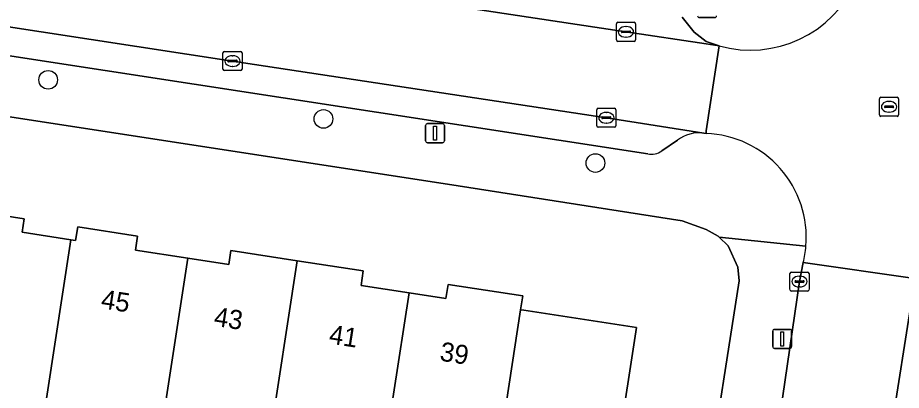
# Model space of a CAD drawing. Extents: x 161483 to 162250, y 379484 to 380833.
# Drawn here: x 161963.9 to 162010.23, y 380518.15 to 380537.71 of the extents above; entities that cross this region are included whole.
import ezdxf

# ---------------------------------------------------------------- set-up
doc = ezdxf.new("R2010")
doc.units = 0
for name, color, linetype in [('IMGEO_Boom', 7, 'Continuous'), ('IMGEO_Erf', 7, 'Continuous'), ('IMGEO_Kolk', 7, 'Continuous'), ('IMGEO_Lichtmast', 7, 'Continuous'), ('IMGEO_Pand', 7, 'Continuous'), ('IMGEO_Pand_nummerreeks', 7, 'Continuous'), ('IMGEO_Parkeervlak_open', 7, 'Continuous'), ('IMGEO_Rijbaan_lokaal_open', 7, 'Continuous'), ('IMGEO_Rioolput', 7, 'Continuous'), ('IMGEO_Voetpad_open', 7, 'Continuous')]:
    doc.layers.add(name, color=color, linetype=linetype)

msp = doc.modelspace()

# ---------------------------------------------------------------- linework, layer by layer
at = {"layer": 'IMGEO_Boom'}
for centre in [(161965.497, 380534.445), (161979.932, 380532.394), (161994.191, 380530.079)]:
    msp.add_circle(centre, 0.489, dxfattribs=at)
at = {"layer": 'IMGEO_Erf'}
for points in [[(162001.728, 380523.906), (162001.658, 380524.62), (162001.144, 380525.735), (162000.674, 380526.189), (162000.627, 380526.234), (162000, 380526.588), (161998.738, 380527.044), (161986.998, 380528.881), (161932.112, 380537.338)], [(161960.869, 380527.668), (161964.235, 380527.151), (161964.127, 380526.446), (161966.695, 380526.052), (161966.94, 380526.014), (161967.05, 380526.73), (161970.184, 380526.248), (161970.069, 380525.501), (161972.814, 380525.079), (161974.966, 380524.748), (161975.079, 380525.482), (161978.56, 380524.947), (161982.017, 380524.415), (161981.901, 380523.66), (161984.425, 380523.272), (161986.351, 380522.976), (161986.464, 380523.708), (161990.381, 380523.106), (161990.27, 380522.381), (161990.445, 380522.354), (161996.342, 380521.448), (161994.423, 380508.962)], [(162000, 380512.813), (162001.728, 380523.906)]]:
    msp.add_lwpolyline(points, dxfattribs=at)
at = {"layer": 'IMGEO_Kolk'}
for p, q in [((161995.292, 380536.539), (161995.292, 380537.391)), ((161995.367, 380537.465), (161996.219, 380537.465)), ((161995.78, 380537.245), (161995.805, 380537.245)), ((161996.293, 380537.391), (161996.293, 380536.539)), ((161995.551, 380536.959), (161995.551, 380536.971)), ((161995.989, 380536.922), (161995.591, 380536.922)), ((161995.594, 380537.008), (161995.992, 380537.008)), ((161996.035, 380536.971), (161996.035, 380536.959)), ((161996.219, 380536.465), (161995.367, 380536.465)), ((161995.803, 380536.685), (161995.778, 380536.685)), ((161974.662, 380535.005), (161974.662, 380535.857)), ((161974.737, 380535.931), (161975.589, 380535.931)), ((161975.663, 380535.857), (161975.663, 380535.005)), ((161974.921, 380535.425), (161974.921, 380535.437)), ((161975.359, 380535.388), (161974.961, 380535.388)), ((161974.964, 380535.474), (161975.362, 380535.474)), ((161975.15, 380535.711), (161975.175, 380535.711)), ((161975.405, 380535.437), (161975.405, 380535.425)), ((161975.589, 380534.931), (161974.737, 380534.931)), ((161975.173, 380535.151), (161975.148, 380535.151)), ((161994.263, 380532.028), (161994.263, 380532.88)), ((161994.338, 380532.954), (161995.19, 380532.954)), ((161994.751, 380532.734), (161994.776, 380532.734)), ((161995.264, 380532.88), (161995.264, 380532.028)), ((161994.522, 380532.448), (161994.522, 380532.46)), ((161994.96, 380532.411), (161994.562, 380532.411)), ((161994.565, 380532.497), (161994.963, 380532.497)), ((161994.774, 380532.174), (161994.749, 380532.174)), ((161995.006, 380532.46), (161995.006, 380532.448)), ((161995.19, 380531.954), (161994.338, 380531.954)), ((162004.389, 380523.434), (162004.389, 380524.286)), ((162004.464, 380524.36), (162005.316, 380524.36)), ((162005.39, 380524.286), (162005.39, 380523.434)), ((162004.648, 380523.854), (162004.648, 380523.866)), ((162005.086, 380523.817), (162004.688, 380523.817)), ((162004.691, 380523.903), (162005.089, 380523.903)), ((162004.877, 380524.14), (162004.902, 380524.14)), ((162005.132, 380523.866), (162005.132, 380523.854)), ((162005.316, 380523.36), (162004.464, 380523.36)), ((162004.9, 380523.58), (162004.875, 380523.58))]:
    msp.add_line(p, q, dxfattribs=at)
for points in [[(161995.292, 380536.539), (161995.292, 380537.391)], [(161995.367, 380537.465), (161996.219, 380537.465)], [(161996.293, 380537.391), (161996.293, 380536.539)], [(161996.219, 380536.465), (161995.367, 380536.465)], [(161974.662, 380535.005), (161974.662, 380535.857)], [(161974.737, 380535.931), (161975.589, 380535.931)], [(161975.663, 380535.857), (161975.663, 380535.005)], [(161975.589, 380534.931), (161974.737, 380534.931)], [(161994.263, 380532.028), (161994.263, 380532.88)], [(161994.338, 380532.954), (161995.19, 380532.954)], [(161995.264, 380532.88), (161995.264, 380532.028)], [(161995.19, 380531.954), (161994.338, 380531.954)], [(162004.389, 380523.434), (162004.389, 380524.286)], [(162004.464, 380524.36), (162005.316, 380524.36)], [(162005.39, 380524.286), (162005.39, 380523.434)], [(162005.316, 380523.36), (162004.464, 380523.36)]]:
    msp.add_lwpolyline(points, dxfattribs=at)
for centre, radius, start, end in [((161995.369, 380537.389), 0.0765, 91.552, 178.448), ((161995.369, 380537.389), 0.0765, 91.552, 178.448), ((161996.217, 380537.389), 0.0765, 1.552, 88.448), ((161996.217, 380537.389), 0.0765, 1.552, 88.448), ((161995.591, 380536.968), 0.0403, 85.8775, 175.7526), ((161995.588, 380536.958), 0.0366, 178.938, 274.7102), ((161995.992, 380536.965), 0.043, 264.8664, 352.4533), ((161995.996, 380536.97), 0.0386, 1.7309, 96.639), ((161995.369, 380536.541), 0.0765, 181.552, 268.448), ((161995.369, 380536.541), 0.0765, 181.552, 268.448), ((161996.217, 380536.541), 0.0765, 271.552, 358.448), ((161996.217, 380536.541), 0.0765, 271.552, 358.448), ((161974.739, 380535.855), 0.0765, 91.552, 178.448), ((161974.739, 380535.855), 0.0765, 91.552, 178.448), ((161975.587, 380535.855), 0.0765, 1.552, 88.448), ((161975.587, 380535.855), 0.0765, 1.552, 88.448), ((161974.961, 380535.434), 0.0403, 85.8775, 175.7526), ((161974.958, 380535.424), 0.0366, 178.938, 274.7102), ((161975.362, 380535.431), 0.043, 264.8664, 352.4533), ((161975.366, 380535.436), 0.0386, 1.7309, 96.639), ((161974.739, 380535.007), 0.0765, 181.552, 268.448), ((161974.739, 380535.007), 0.0765, 181.552, 268.448), ((161975.587, 380535.007), 0.0765, 271.552, 358.448), ((161975.587, 380535.007), 0.0765, 271.552, 358.448), ((161994.34, 380532.878), 0.0765, 91.552, 178.448), ((161994.34, 380532.878), 0.0765, 91.552, 178.448), ((161995.188, 380532.878), 0.0765, 1.552, 88.448), ((161995.188, 380532.878), 0.0765, 1.552, 88.448), ((161994.562, 380532.457), 0.0403, 85.8775, 175.7526), ((161994.559, 380532.447), 0.0366, 178.938, 274.7102), ((161994.963, 380532.454), 0.043, 264.8664, 352.4533), ((161994.967, 380532.459), 0.0386, 1.7309, 96.639), ((161994.34, 380532.03), 0.0765, 181.552, 268.448), ((161994.34, 380532.03), 0.0765, 181.552, 268.448), ((161995.188, 380532.03), 0.0765, 271.552, 358.448), ((161995.188, 380532.03), 0.0765, 271.552, 358.448), ((162004.466, 380524.284), 0.0765, 91.552, 178.448), ((162004.466, 380524.284), 0.0765, 91.552, 178.448), ((162005.314, 380524.284), 0.0765, 1.552, 88.448), ((162005.314, 380524.284), 0.0765, 1.552, 88.448), ((162004.688, 380523.863), 0.0403, 85.8775, 175.7526), ((162004.685, 380523.853), 0.0366, 178.938, 274.7102), ((162005.089, 380523.86), 0.043, 264.8664, 352.4533), ((162005.093, 380523.865), 0.0386, 1.7309, 96.639), ((162004.466, 380523.436), 0.0765, 181.552, 268.448), ((162004.466, 380523.436), 0.0765, 181.552, 268.448), ((162005.314, 380523.436), 0.0765, 271.552, 358.448), ((162005.314, 380523.436), 0.0765, 271.552, 358.448)]:
    msp.add_arc(centre, radius, start, end, dxfattribs=at)
for centre, major_axis, ratio, start_param, end_param in [((161995.779, 380536.965), (-0.387, 0.002), 0.722429, 4.712389, 7.853982), ((161995.804, 380536.965), (-0.39, 0.002), 0.717154, 1.570796, 4.712389), ((161975.149, 380535.431), (-0.387, 0.002), 0.722429, 4.712389, 7.853982), ((161975.174, 380535.431), (-0.39, 0.002), 0.717154, 1.570796, 4.712389), ((161994.75, 380532.454), (-0.387, 0.002), 0.722429, 4.712389, 7.853982), ((161994.775, 380532.454), (-0.39, 0.002), 0.717154, 1.570796, 4.712389), ((162004.876, 380523.86), (-0.387, 0.002), 0.722429, 4.712389, 7.853982), ((162004.901, 380523.86), (-0.39, 0.002), 0.717154, 1.570796, 4.712389)]:
    msp.add_ellipse(centre, major_axis=major_axis, ratio=ratio, start_param=start_param, end_param=end_param, dxfattribs=at)
at = {"layer": 'IMGEO_Lichtmast'}
for p, q in [((162000.439, 380537.709), (161999.649, 380537.709)), ((161999.649, 380537.709), (162000.439, 380537.709)), ((161985.386, 380532.148), (161986.176, 380532.148)), ((161986.176, 380532.148), (161985.386, 380532.148)), ((161985.286, 380531.248), (161985.286, 380532.048)), ((161985.286, 380532.048), (161985.286, 380531.248)), ((161986.276, 380532.048), (161986.276, 380531.248)), ((161986.276, 380531.248), (161986.276, 380532.048)), ((161986.176, 380531.148), (161985.386, 380531.148)), ((161985.386, 380531.148), (161986.176, 380531.148)), ((162003.485, 380520.448), (162003.485, 380521.248)), ((162003.485, 380521.248), (162003.485, 380520.448)), ((162003.585, 380521.348), (162004.375, 380521.348)), ((162004.375, 380521.348), (162003.585, 380521.348)), ((162004.475, 380521.248), (162004.475, 380520.448)), ((162004.475, 380520.448), (162004.475, 380521.248)), ((162004.375, 380520.348), (162003.585, 380520.348)), ((162003.585, 380520.348), (162004.375, 380520.348))]:
    msp.add_line(p, q, dxfattribs=at)
for points in [[(161985.706, 380532.023), (161985.856, 380532.023), (161985.856, 380531.273), (161985.706, 380531.273), (161985.706, 380532.023)], [(162003.905, 380521.223), (162004.055, 380521.223), (162004.055, 380520.473), (162003.905, 380520.473), (162003.905, 380521.223)]]:
    msp.add_lwpolyline(points, dxfattribs=at)
for centre, start, end in [((161999.649, 380537.809), 180, 270), ((161999.649, 380537.809), 180, 270), ((162000.439, 380537.809), 270, 0), ((162000.439, 380537.809), 270, 0), ((161985.386, 380532.048), 90, 180), ((161985.386, 380532.048), 90, 180), ((161986.176, 380532.048), 0, 90), ((161986.176, 380532.048), 360, 90), ((161985.386, 380531.248), 180, 270), ((161985.386, 380531.248), 180, 270), ((161986.176, 380531.248), 270, 0), ((161986.176, 380531.248), 270, 0), ((162003.585, 380521.248), 90, 180), ((162003.585, 380521.248), 90, 180), ((162004.375, 380521.248), 0, 90), ((162004.375, 380521.248), 360, 90), ((162003.585, 380520.448), 180, 270), ((162003.585, 380520.448), 180, 270), ((162004.375, 380520.448), 270, 0), ((162004.375, 380520.448), 270, 0)]:
    msp.add_arc(centre, 0.1, start, end, dxfattribs=at)
at = {"layer": 'IMGEO_Pand'}
for points in [[(161966.695, 380526.052), (161964.127, 380526.446), (161964.235, 380527.151), (161960.869, 380527.668), (161959.381, 380517.981), (161959.162, 380516.28), (161959.156, 380516.237), (161965.048, 380515.332)], [(161972.814, 380525.079), (161970.069, 380525.501), (161970.184, 380526.248), (161967.05, 380526.73), (161966.94, 380526.014), (161966.695, 380526.052), (161965.048, 380515.332), (161965.15, 380515.316), (161968.125, 380514.865), (161971.173, 380514.397)], [(161978.56, 380524.947), (161975.079, 380525.482), (161974.966, 380524.748), (161972.814, 380525.079), (161971.173, 380514.397), (161973.602, 380514.024), (161976.807, 380513.532), (161977.073, 380515.263)], [(161977.073, 380515.263), (161980.139, 380514.792), (161979.877, 380513.082), (161982.791, 380512.634), (161984.425, 380523.272), (161981.901, 380523.66), (161982.017, 380524.415), (161978.56, 380524.947)], [(161990.27, 380522.381), (161990.381, 380523.106), (161986.464, 380523.708), (161986.351, 380522.976), (161984.425, 380523.272), (161982.791, 380512.634), (161982.508, 380510.793), (161988.352, 380509.895), (161988.911, 380513.534)], [(161996.342, 380521.448), (161990.445, 380522.354), (161990.27, 380522.381), (161988.911, 380513.534), (161988.352, 380509.895), (161991.806, 380509.364), (161994.423, 380508.962)]]:
    msp.add_lwpolyline(points, close=True, dxfattribs=at)
at = {"layer": 'IMGEO_Parkeervlak_open'}
for points in [[(161929.69, 380547.086), (161933.264, 380546.55), (161935.372, 380546.247), (161952.528, 380543.603), (161973.878, 380540.297), (161995.793, 380536.963), (162000, 380536.329), (162000.684, 380536.226), (162000, 380536.452), (161999.367, 380536.946), (161998.747, 380537.733)], [(161999.874, 380531.653), (161994.763, 380532.455), (161975.164, 380535.431), (161952.685, 380538.893), (161936.805, 380541.351), (161932.606, 380542.007)], [(161935.118, 380540.075), (161996.932, 380530.558)], [(161997.666, 380530.714), (161998.496, 380531.281)]]:
    msp.add_lwpolyline(points, dxfattribs=at)
for centre, radius, start, end in [((161999.638, 380529.787), 1.881, 82.8041, 127.4104), ((161997.108, 380531.536), 0.994, 259.818, 304.1795)]:
    msp.add_arc(centre, radius, start, end, dxfattribs=at)
at = {"layer": 'IMGEO_Rijbaan_lokaal_open'}
msp.add_lwpolyline([(161933.264, 380546.55), (161932.606, 380542.007), (161936.805, 380541.351), (161952.685, 380538.893), (161975.164, 380535.431), (161994.763, 380532.455), (161999.874, 380531.653), (162000, 380531.633), (162000, 380531.772), (162000.684, 380536.226), (162000, 380536.329), (161995.793, 380536.963), (161973.878, 380540.297), (161952.528, 380543.603), (161935.372, 380546.247)], close=True, dxfattribs=at)
for points in [[(162000.684, 380536.226), (162000, 380531.772), (162000, 380531.633)], [(162005.978, 380491.592), (162006.784, 380496.829), (162007.271, 380500), (162009.728, 380516.285), (162010.756, 380522.832), (162010.932, 380524.02), (162005.085, 380524.854), (162004.891, 380523.86), (162003.878, 380516.894), (162001.249, 380500), (162000.753, 380496.771), (162000.066, 380492.294), (162000, 380492.002), (161999.789, 380491.531), (161999.389, 380490.794), (161999.112, 380490.027), (161990.029, 380431.608)], [(162005.085, 380524.854), (162010.932, 380524.02)]]:
    msp.add_lwpolyline(points, dxfattribs=at)
for centre, radius, start, end in [((162002.309, 380542.092), 6.087, 254.5191, 335.7592), ((161999.786, 380526.176), 5.461, 355.1673, 87.7575), ((161999.863, 380526.163), 5.384, 345.9264, 355.2352)]:
    msp.add_arc(centre, radius, start, end, dxfattribs=at)
at = {"layer": 'IMGEO_Rioolput'}
for p, q in [((162009.16, 380533.531), (162010.012, 380533.531)), ((162009.085, 380532.605), (162009.085, 380533.457)), ((162009.387, 380533.074), (162009.785, 380533.074)), ((162009.573, 380533.311), (162009.598, 380533.311)), ((162010.086, 380533.457), (162010.086, 380532.605)), ((162009.344, 380533.025), (162009.344, 380533.037)), ((162009.782, 380532.988), (162009.384, 380532.988)), ((162009.596, 380532.751), (162009.571, 380532.751)), ((162009.828, 380533.037), (162009.828, 380533.025)), ((162010.012, 380532.531), (162009.16, 380532.531))]:
    msp.add_line(p, q, dxfattribs=at)
for points in [[(162009.16, 380533.531), (162010.012, 380533.531)], [(162009.085, 380532.605), (162009.085, 380533.457)], [(162010.086, 380533.457), (162010.086, 380532.605)], [(162010.012, 380532.531), (162009.16, 380532.531)]]:
    msp.add_lwpolyline(points, dxfattribs=at)
for centre, radius, start, end in [((162009.162, 380533.455), 0.0765, 91.552, 178.448), ((162009.162, 380533.455), 0.0765, 91.552, 178.448), ((162010.01, 380533.455), 0.0765, 1.552, 88.448), ((162010.01, 380533.455), 0.0765, 1.552, 88.448), ((162009.384, 380533.034), 0.0403, 85.8775, 175.7526), ((162009.789, 380533.036), 0.0386, 1.7309, 96.639), ((162009.162, 380532.607), 0.0765, 181.552, 268.448), ((162009.162, 380532.607), 0.0765, 181.552, 268.448), ((162009.381, 380533.024), 0.0366, 178.938, 274.7102), ((162009.785, 380533.031), 0.043, 264.8664, 352.4533), ((162010.01, 380532.607), 0.0765, 271.552, 358.448), ((162010.01, 380532.607), 0.0765, 271.552, 358.448)]:
    msp.add_arc(centre, radius, start, end, dxfattribs=at)
for centre, major_axis, ratio, start_param, end_param in [((162009.572, 380533.031), (-0.387, 0.002), 0.722429, 4.712389, 7.853982), ((162009.597, 380533.031), (-0.39, 0.002), 0.717154, 1.570796, 4.712389)]:
    msp.add_ellipse(centre, major_axis=major_axis, ratio=ratio, start_param=start_param, end_param=end_param, dxfattribs=at)
at = {"layer": 'IMGEO_Voetpad_open'}
for points in [[(161996.932, 380530.558), (161935.118, 380540.075)], [(161998.747, 380537.733), (161999.367, 380536.946), (162000, 380536.452), (162000.684, 380536.226)], [(161932.112, 380537.338), (161986.998, 380528.881), (161998.738, 380527.044), (162000, 380526.588), (162000.627, 380526.234), (162000.674, 380526.189), (162005.228, 380525.716)], [(161998.496, 380531.281), (161997.666, 380530.714)], [(162000, 380531.633), (161999.874, 380531.653)], [(162005.228, 380525.716), (162000.674, 380526.189), (162001.144, 380525.735), (162001.658, 380524.62), (162001.728, 380523.906), (162000, 380512.813), (161998.03, 380500), (161997.539, 380496.804), (161997.393, 380495.855), (161982.918, 380401.702)], [(161990.029, 380431.608), (161999.112, 380490.027), (161999.389, 380490.794), (161999.789, 380491.531), (162000, 380492.002), (162000.066, 380492.294), (161999.572, 380492.37), (162000, 380495.135), (162000.265, 380496.846), (162000.753, 380496.771), (162001.249, 380500), (162003.878, 380516.894), (162004.891, 380523.86), (162005.085, 380524.854)], [(162009.269, 380494.234), (162009.511, 380495.807), (162010.156, 380500), (162013.459, 380521.47), (162013.988, 380522.858), (162010.932, 380524.02), (162010.756, 380522.832), (162009.728, 380516.285), (162007.271, 380500), (162006.784, 380496.829), (162007.267, 380496.756), (162006.472, 380491.517), (162005.978, 380491.592)]]:
    msp.add_lwpolyline(points, dxfattribs=at)
for centre, radius, start, end in [((162002.309, 380542.092), 6.087, 254.5191, 335.7592), ((161999.638, 380529.787), 1.881, 82.8041, 127.4104), ((161999.786, 380526.176), 5.461, 355.1673, 87.7575), ((161997.108, 380531.536), 0.994, 259.818, 304.1795), ((161999.863, 380526.163), 5.384, 345.9264, 355.2352)]:
    msp.add_arc(centre, radius, start, end, dxfattribs=at)

# ---------------------------------------------------------------- texts
at = {"layer": 'IMGEO_Pand_nummerreeks'}
for s, rotation, p in [('45', 351.2108, (161968.227, 380522.462)), ('43', 351.2108, (161974.148, 380521.547)), ('41', 351.2104, (161980.181, 380520.615)), ('39', 351.2108, (161985.99, 380519.716))]:
    msp.add_text(s, height=1, rotation=rotation, dxfattribs=at).set_placement(p)

doc.saveas('drawing.dxf')
